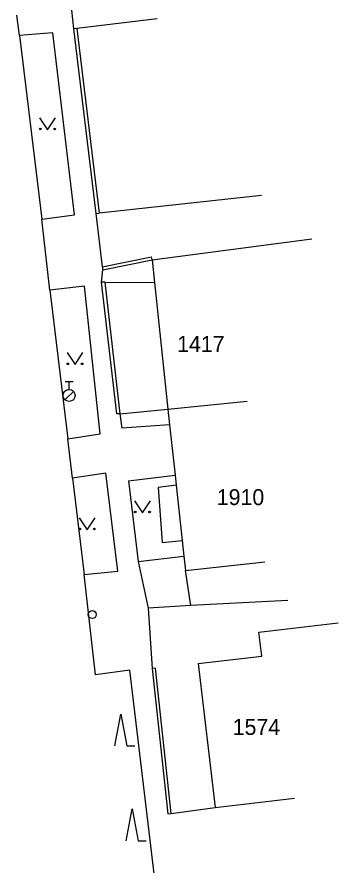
# Model space of a CAD drawing. Extents: x -539515 to -538098, y -1182060 to -1180157.
# Drawn here: x -539478.4 to -539458.3, y -1180484.4 to -1180431.3 of the extents above; entities that cross this region are included whole.
import ezdxf

# ---------------------------------------------------------------- set-up
doc = ezdxf.new("R2010")
doc.units = 0
for name, color, linetype in [('Vrstva 1', 7, 'Continuous'), ('Vrstva 11', 7, 'Continuous'), ('Vrstva 13', 7, 'Continuous'), ('Vrstva 28', 7, 'Continuous'), ('Vrstva 36', 7, 'Continuous'), ('Vrstva 47', 7, 'Continuous'), ('Vrstva 68', 7, 'Continuous'), ('Vrstva 88', 7, 'Continuous')]:
    doc.layers.add(name, color=color, linetype=linetype)

msp = doc.modelspace()

# ---------------------------------------------------------------- linework, layer by layer
at = {"layer": 'Vrstva 1'}
for p, q in [((-539469.96, -1180446.508), (-539459.95, -1180445.188)), ((-539469.96, -1180446.508), (-539469.812, -1180447.923)), ((-539469.812, -1180447.923), (-539468.98, -1180455.867)), ((-539468.98, -1180455.867), (-539464.006, -1180455.359)), ((-539468.98, -1180455.867), (-539468.868, -1180456.849)), ((-539468.868, -1180456.849), (-539468.511, -1180459.99)), ((-539468.511, -1180459.99), (-539468.44, -1180460.617)), ((-539468.44, -1180460.617), (-539469.58, -1180460.773)), ((-539469.58, -1180460.773), (-539469.32, -1180464.211)), ((-539468.44, -1180460.617), (-539468.065, -1180464.078)), ((-539469.32, -1180464.211), (-539468.065, -1180464.078)), ((-539468.065, -1180464.078), (-539467.959, -1180465.056)), ((-539467.959, -1180465.056), (-539467.86, -1180465.969)), ((-539467.86, -1180465.969), (-539462.891, -1180465.422)), ((-539463.265, -1180469.828), (-539458.299, -1180469.242)), ((-539463.087, -1180471.32), (-539463.265, -1180469.828)), ((-539467.06, -1180471.789), (-539463.087, -1180471.32)), ((-539467.06, -1180471.789), (-539466, -1180480.797)), ((-539466, -1180480.797), (-539461.034, -1180480.211))]:
    msp.add_line(p, q, dxfattribs=at)
at = {"layer": 'Vrstva 11'}
msp.add_line((-539470.2, -1180468.32), (-539469.95, -1180472.094), dxfattribs=at)
at = {"layer": 'Vrstva 13'}
for p, q in [((-539469.641, -1180431.406), (-539474.682, -1180432.023)), ((-539476.17, -1180432.289), (-539478.28, -1180432.453)), ((-539474.83, -1180443.688), (-539476.17, -1180432.289)), ((-539476.88, -1180443.953), (-539474.83, -1180443.688)), ((-539473.13, -1180447.914), (-539473.04, -1180447.133)), ((-539474.2, -1180448.148), (-539476.36, -1180448.406)), ((-539473.22, -1180457.406), (-539474.2, -1180448.148)), ((-539472.93, -1180447.898), (-539469.812, -1180447.923)), ((-539468.868, -1180456.849), (-539471.85, -1180457.04)), ((-539475.24, -1180457.719), (-539473.22, -1180457.406)), ((-539472.85, -1180459.867), (-539474.95, -1180460.188)), ((-539472.11, -1180466), (-539472.85, -1180459.867)), ((-539471.43, -1180460.352), (-539468.511, -1180459.99)), ((-539470.82, -1180465.406), (-539467.959, -1180465.056)), ((-539474.22, -1180466.219), (-539472.11, -1180466)), ((-539467.53, -1180468.148), (-539467.86, -1180465.969)), ((-539471.35, -1180472.203), (-539473.5, -1180472.492)), ((-539468.75, -1180494.039), (-539471.35, -1180472.203))]:
    msp.add_line(p, q, dxfattribs=at)
at = {"layer": 'Vrstva 28'}
for p, q in [((-539475.41, -1180454.125), (-539474.91, -1180454.125)), ((-539475.16, -1180454.625), (-539475.16, -1180454.125)), ((-539475.418, -1180455.272), (-539474.888, -1180454.742))]:
    msp.add_line(p, q, dxfattribs=at)
for centre, radius in [((-539475.16, -1180455), 0.375), ((-539473.71, -1180468.719), 0.25)]:
    msp.add_circle(centre, radius, dxfattribs=at)
at = {"layer": 'Vrstva 36'}
for points in [[(-539477.016, -1180437.609), (-539476.516, -1180438.359), (-539476.016, -1180437.609)], [(-539475.289, -1180452.32), (-539474.789, -1180453.07), (-539474.289, -1180452.32)], [(-539471.066, -1180461.594), (-539470.566, -1180462.344), (-539470.066, -1180461.594)], [(-539474.521, -1180462.664), (-539474.021, -1180463.414), (-539473.521, -1180462.664)], [(-539472.292, -1180476.95), (-539471.917, -1180474.95), (-539471.542, -1180476.95), (-539471.042, -1180476.95)], [(-539471.584, -1180482.895), (-539471.209, -1180480.895), (-539470.834, -1180482.895), (-539470.334, -1180482.895)]]:
    msp.add_lwpolyline(points, dxfattribs=at)
for centre in [(-539476.966, -1180438.309), (-539476.067, -1180438.309), (-539475.239, -1180453.02), (-539474.34, -1180453.02), (-539471.016, -1180462.294), (-539470.117, -1180462.294), (-539474.471, -1180463.364), (-539473.572, -1180463.364)]:
    msp.add_circle(centre, 0.05, dxfattribs=at)
at = {"layer": 'Vrstva 68'}
for p, q in [((-539475.01, -1180430.867), (-539474.88, -1180432.047)), ((-539474.682, -1180432.023), (-539474.88, -1180432.047)), ((-539474.88, -1180432.047), (-539473.48, -1180443.602)), ((-539474.682, -1180432.023), (-539473.282, -1180443.578)), ((-539463.09, -1180442.477), (-539473.282, -1180443.578)), ((-539473.48, -1180443.602), (-539473.282, -1180443.578)), ((-539473.48, -1180443.602), (-539473.08, -1180446.938)), ((-539473.08, -1180446.938), (-539470, -1180446.313)), ((-539473.04, -1180447.133), (-539469.96, -1180446.508)), ((-539469.96, -1180446.508), (-539470, -1180446.313)), ((-539473.08, -1180446.938), (-539473.04, -1180447.133)), ((-539472.93, -1180447.898), (-539473.13, -1180447.914)), ((-539472.17, -1180456.156), (-539473.13, -1180447.914)), ((-539472.93, -1180447.898), (-539471.97, -1180456.141)), ((-539471.97, -1180456.141), (-539472.17, -1180456.156)), ((-539471.97, -1180456.141), (-539468.98, -1180455.867)), ((-539471.97, -1180456.141), (-539471.85, -1180457.04)), ((-539471.43, -1180460.352), (-539470.82, -1180465.406)), ((-539470.82, -1180465.406), (-539470.2, -1180468.32)), ((-539461.451, -1180467.844), (-539467.53, -1180468.148)), ((-539467.53, -1180468.148), (-539470.2, -1180468.32)), ((-539469.751, -1180472.07), (-539469.95, -1180472.094)), ((-539469.95, -1180472.094), (-539468.97, -1180481.203)), ((-539468.771, -1180481.18), (-539469.751, -1180472.07)), ((-539468.97, -1180481.203), (-539468.771, -1180481.18)), ((-539468.771, -1180481.18), (-539466, -1180480.797))]:
    msp.add_line(p, q, dxfattribs=at)
at = {"layer": 'Vrstva 88'}
for p, q in [((-539478.28, -1180432.453), (-539478.43, -1180431.188)), ((-539478.28, -1180432.453), (-539476.88, -1180443.953)), ((-539476.36, -1180448.406), (-539476.88, -1180443.953)), ((-539476.36, -1180448.406), (-539475.24, -1180457.719)), ((-539474.95, -1180460.188), (-539475.24, -1180457.719)), ((-539474.95, -1180460.188), (-539474.22, -1180466.219)), ((-539473.5, -1180472.492), (-539474.22, -1180466.219))]:
    msp.add_line(p, q, dxfattribs=at)

# ---------------------------------------------------------------- texts
at = {"layer": 'Vrstva 47'}
for s, p in [('1417', (-539468.387, -1180452.273)), ('1910', (-539465.901, -1180461.867)), ('1574', (-539464.905, -1180476.258))]:
    msp.add_text(s, height=1, dxfattribs=at).set_placement(p)

doc.saveas('drawing.dxf')
